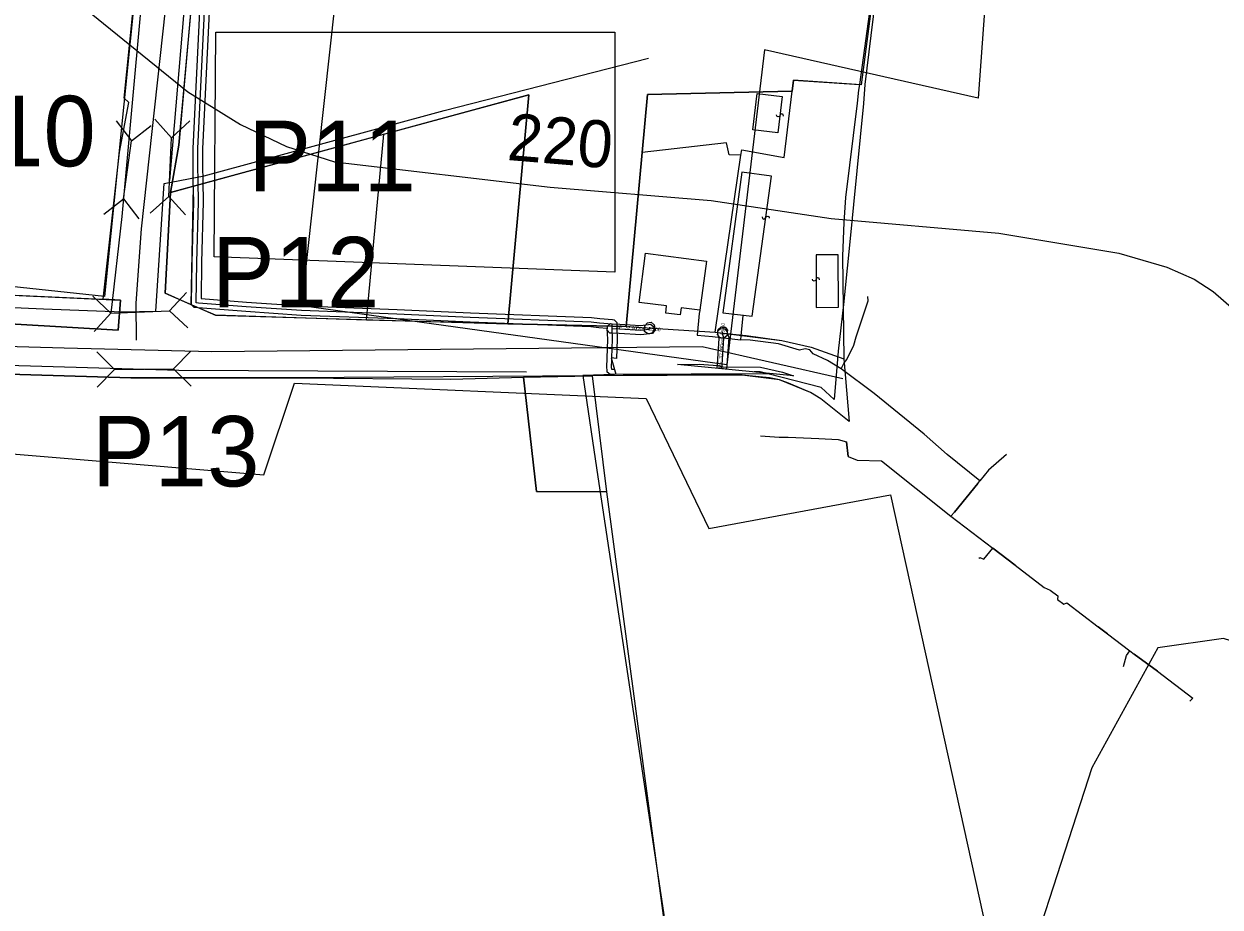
# Model space of a CAD drawing. Extents: x -662500 to -655523, y -1056000 to -1049993.
# Drawn here: x -660179.8 to -659925.2, y -1053965.2 to -1053777.2 of the extents above; entities that cross this region are included whole.
import ezdxf

# ---------------------------------------------------------------- set-up
doc = ezdxf.new("R2010")
doc.units = 0
for name, color, linetype in [('58', 7, 'Continuous'), ('Implicitní', 7, 'Continuous'), ('Vrstva 1', 7, 'Continuous'), ('Vrstva 11', 7, 'Continuous'), ('Vrstva 17', 7, 'Continuous'), ('Vrstva 24', 7, 'Continuous'), ('Vrstva 32', 7, 'Continuous'), ('Vrstva 37', 7, 'Continuous'), ('Vrstva 42', 7, 'Continuous'), ('Vrstva 45', 7, 'Continuous'), ('Vrstva 47', 7, 'Continuous'), ('Vrstva 48', 7, 'Continuous'), ('Vrstva 5', 7, 'Continuous'), ('Vrstva 61', 7, 'Continuous'), ('Vrstva 7', 7, 'Continuous')]:
    doc.layers.add(name, color=color, linetype=linetype)

# ---------------------------------------------------------------- blocks, each defined once
blk = doc.blocks.new('PSZ017')
at = {"layer": 'Vrstva 17'}
for points in [[(-10, 3.75), (-6.25, 0), (-10, -3.75)], [(10, 3.75), (6.25, 0), (10, -3.75)], [(-6.25, 0), (6.25, 0)]]:
    blk.add_lwpolyline(points, dxfattribs=at)
blk = doc.blocks.new('POINT_DISPLAY')
at = {"layer": 'Implicitní'}
blk.add_line((0, 0), (0, 0), dxfattribs=at)
blk = doc.blocks.new('$364')
at = {"layer": 'Implicitní'}
blk.add_lwpolyline([(-0.5, -7.5), (2.5, -6.5), (3.7, -3.4), (2.3, -0.7), (-2.5, 1), (-3.7, 3.8), (-2.3, 6.7), (0.5, 7.5)], dxfattribs=at)

msp = doc.modelspace()

# ---------------------------------------------------------------- linework, layer by layer
at = {"layer": '58'}
msp.add_lwpolyline([(-659966.09, -1053589.8), (-659979.45, -1053646.11), (-659986.05, -1053669.16), (-659992.56, -1053722.27), (-660000.86, -1053790.13), (-660001.11, -1053794.15), (-660003.29, -1053815.65), (-660003.85, -1053821.48), (-660005.39, -1053836.92), (-660006.52, -1053846.84), (-660007.35, -1053857.17), (-660010.12, -1053854.58), (-660021.49, -1053851.7), (-660054.09, -1053851.84), (-660060.83, -1053852), (-660057.69, -1053873.59), (-660041.94, -1053978.1)], dxfattribs=at)
at = {"layer": 'Vrstva 1'}
for p, q in [((-660106.89, -1053840.23), (-660103.21, -1053800.71)), ((-660144.25, -1053836.96), (-660143.69, -1053811.76))]:
    msp.add_line(p, q, dxfattribs=at)
for points in [[(-659954.06, -1053529.13), (-659973.69, -1053620.54), (-659985.28, -1053668.78), (-660002.01, -1053790.13), (-660002.16, -1053791.32), (-660002.5, -1053794.1), (-660004.94, -1053814.14), (-660005.18, -1053817.33), (-660005.34, -1053819.44), (-660005.58, -1053826.65), (-660005.29, -1053848.46), (-660004.16, -1053861.83), (-660010.2, -1053857.03), (-660012.44, -1053855.66), (-660017.12, -1053853.66), (-660019.03, -1053852.98), (-660021.16, -1053852.5), (-660026.92, -1053851.95), (-660035.99, -1053851.88), (-660050.1, -1053852.01), (-660052.3, -1053852.03), (-660058.85, -1053852.09), (-660055.8, -1053876.8), (-660042.1, -1053979.18)], [(-660051.64, -1053841.59), (-660048.25, -1053804.57), (-660047.13, -1053792.26), (-660016.34, -1053791.52), (-660016.06, -1053789.15), (-660002.01, -1053790.13)], [(-660032.72, -1053842.78), (-660027.21, -1053805.13), (-660027.04, -1053803.99), (-660017.98, -1053805.64), (-660016.34, -1053791.52)], [(-660027.21, -1053805.13), (-660029.72, -1053805.1), (-660030.32, -1053802.52), (-660048.25, -1053804.57)], [(-660051.64, -1053841.59), (-660032.72, -1053842.78), (-660031.72, -1053842.95), (-660026.12, -1053843.5), (-660018.51, -1053844.59), (-660012.27, -1053845.97), (-660005.29, -1053848.46)], [(-660055.8, -1053876.8), (-660070.7, -1053876.72), (-660073.51, -1053852.41), (-660058.85, -1053852.09)]]:
    msp.add_lwpolyline(points, dxfattribs=at)
for points in [[(-660148.64, -1053813.09), (-660143.69, -1053811.76), (-660103.21, -1053800.71), (-660072.33, -1053792.31), (-660076.83, -1053841.01), (-660106.89, -1053840.23), (-660139.06, -1053839.19), (-660144.25, -1053836.96), (-660149.76, -1053834.51)], [(-660023.73, -1053792.04), (-660018.42, -1053792.64), (-660019.34, -1053800.39), (-660024.7, -1053799.73)], [(-660027, -1053808.74), (-660031.07, -1053838.68), (-660024.79, -1053839.44), (-660020.73, -1053809.6)], [(-660047.53, -1053826.01), (-660034.52, -1053827.69), (-660035.98, -1053838.12), (-660039.93, -1053837.64), (-660040.15, -1053839.14), (-660043.23, -1053838.74), (-660043.04, -1053837.23), (-660048.89, -1053836.48)], [(-660011.23, -1053826.37), (-660011.22, -1053837.53), (-660006.47, -1053837.52), (-660006.5, -1053826.37)]]:
    msp.add_lwpolyline(points, close=True, dxfattribs=at)
at = {"layer": 'Vrstva 11'}
for points in [[(-660128.59, -1053535.41), (-660141.02, -1053666.13), (-660149.73, -1053774.2), (-660154.88, -1053820.83), (-660155.97, -1053836.63), (-660155.9, -1053844.5)], [(-660411.52, -1053823.45), (-660373.44, -1053828.35), (-660238.99, -1053844.22), (-660171.25, -1053846.11), (-660139.82, -1053846.95), (-660035.43, -1053845.88), (-660005.55, -1053852.66)]]:
    msp.add_lwpolyline(points, dxfattribs=at)
at = {"layer": 'Vrstva 17'}
for points in [[(-660093.08, -1053291.6), (-660096.38, -1053299.54), (-660103.97, -1053335.5), (-660111.56, -1053371.46), (-660148.84, -1053810.53)], [(-660409.95, -1053827.36), (-660292, -1053842.62), (-660239.28, -1053848.23), (-660146.85, -1053850.88), (-660072.84, -1053851.25)]]:
    msp.add_lwpolyline(points, dxfattribs=at)
at = {"layer": 'Vrstva 24'}
msp.add_lwpolyline([(-659830.33, -1054000), (-659832, -1053994), (-659843, -1053971.5), (-659874, -1053940), (-659913.5, -1053911.5), (-659924.5, -1053908), (-659938.5, -1053910), (-659952.5, -1053935.5), (-659971.5, -1053994), (-659976.58, -1054000)], dxfattribs=at)
at = {"layer": 'Vrstva 32'}
msp.add_lwpolyline([(-660407.56, -1053817.63), (-660406.83, -1053817.81), (-660364.13, -1053822.72), (-660321.75, -1053826.98), (-660286.16, -1053830.17), (-660234.71, -1053835.24), (-660175.64, -1053837.86), (-660158.79, -1053838.51), (-660151.75, -1053838.35), (-660149.96, -1053811.19), (-660141.45, -1053809.55), (-660090.4, -1053795.64), (-660046.88, -1053784.52)], dxfattribs=at)
at = {"layer": 'Vrstva 37'}
for points in [[(-660303.5, -1053230.44), (-660268.36, -1053230.44), (-660272.06, -1053456.27), (-660238.23, -1053464.08), (-660230.1, -1053441.95), (-660156.9, -1053423.64), (-660133.56, -1053315.41), (-660112.26, -1053315.31), (-660122.32, -1053372.39), (-660125.43, -1053404.18), (-660127.57, -1053442.13), (-660131.64, -1053497.5), (-660136.95, -1053566.03), (-660150.34, -1053712.33), (-660162.69, -1053835.19), (-660383.93, -1053811.56), (-660351.89, -1053606.5)], [(-660096.66, -1053668.18), (-659966.86, -1053657.36), (-659976.74, -1053792.99), (-660022.22, -1053782.75), (-660030.23, -1053849.74), (-660120.67, -1053837.24), (-660108.76, -1053729.2)], [(-660389.4, -1053839.98), (-660253.75, -1053862.77), (-660128.74, -1053873.18), (-660122.24, -1053853.65), (-660047.41, -1053856.91), (-660034.08, -1053884.58), (-659995.36, -1053877.42), (-659962.61, -1054026.33), (-660034.34, -1054033.17), (-660165.85, -1054002.41), (-660409.51, -1053977.34)]]:
    msp.add_lwpolyline(points, close=True, dxfattribs=at)
at = {"layer": 'Vrstva 42'}
for p, q in [((-660054.56, -1053844.32), (-660054.65, -1053842.02)), ((-660031.15, -1053843.07), (-660031.11, -1053842.73)), ((-660054.69, -1053848.29), (-660054.56, -1053844.32)), ((-660054.75, -1053850.28), (-660054.7, -1053848.69))]:
    msp.add_line(p, q, dxfattribs=at)
for points in [[(-660142.78, -1053807.34), (-660142.8, -1053803.76), (-660140.36, -1053754.17), (-660137.85, -1053724), (-660136.78, -1053713.11), (-660133.93, -1053679.11), (-660128.02, -1053621.83), (-660127.49, -1053612.47), (-660120.96, -1053547.99), (-660119.87, -1053525.87), (-660118.25, -1053505.95), (-660116.02, -1053485.23), (-660115.83, -1053483.2)], [(-660142.66, -1053836.62), (-660143.12, -1053836.59), (-660143.01, -1053828), (-660142.63, -1053815.06), (-660142.76, -1053810.73), (-660142.78, -1053807.34)], [(-660054.65, -1053842.02), (-660054.64, -1053841.13), (-660057.34, -1053840.88), (-660059.11, -1053840.7), (-660084.83, -1053839.68), (-660100.44, -1053838.97), (-660120.72, -1053838.23), (-660132.51, -1053837.4), (-660142.66, -1053836.62)], [(-660054.65, -1053842.02), (-660053.07, -1053842.11), (-660048.58, -1053842.38), (-660046.77, -1053842.15)], [(-660046.77, -1053842.15), (-660046.56, -1053842.12), (-660046.6, -1053841.74)], [(-660030.82, -1053844.06), (-660031.15, -1053843.11), (-660031.15, -1053843.07)], [(-660031.29, -1053850.59), (-660031.22, -1053849.67), (-660030.82, -1053844.06)], [(-660054.11, -1053850.77), (-660054.7, -1053850.79), (-660054.75, -1053850.28)], [(-660022.27, -1053851.47), (-660023.14, -1053851.27), (-660024.42, -1053851.26)]]:
    msp.add_lwpolyline(points, dxfattribs=at)
for points in [[(-660047.76, -1053842.27), (-660047.82, -1053841.86), (-660047.62, -1053841.61), (-660047.64, -1053841.43), (-660047.12, -1053840.79), (-660046.71, -1053840.74), (-660046.3, -1053840.7), (-660045.65, -1053841.22), (-660045.61, -1053841.63), (-660045.57, -1053842.01), (-660045.52, -1053842.42), (-660046.03, -1053843.06), (-660046.43, -1053843.11), (-660046.64, -1053843.14), (-660047.05, -1053843.19), (-660047.71, -1053842.69)], [(-660055.62, -1053841.55), (-660055, -1053841), (-660054.59, -1053841.02), (-660053.01, -1053841.11), (-660048.61, -1053841.37), (-660046.9, -1053841.16), (-660046.49, -1053841.1), (-660045.83, -1053841.61), (-660045.78, -1053842.02), (-660045.72, -1053842.43), (-660046.23, -1053843.09), (-660046.64, -1053843.14), (-660048.55, -1053843.38), (-660053.13, -1053843.11), (-660054.7, -1053843.02), (-660055.12, -1053842.99), (-660055.67, -1053842.37), (-660055.64, -1053841.96)], [(-660030.28, -1053850.69), (-660032.29, -1053850.49), (-660032.22, -1053849.59), (-660031.83, -1053844.19), (-660032.16, -1053843.23), (-660032.14, -1053842.99), (-660032.1, -1053842.57), (-660031.47, -1053842.04), (-660031.06, -1053842.08), (-660030.64, -1053842.11), (-660030.11, -1053842.75), (-660030.13, -1053842.98), (-660029.81, -1053843.92), (-660030.23, -1053849.74), (-660030.29, -1053850.63)], [(-660031.66, -1053844.03), (-660032.18, -1053843.38), (-660032.14, -1053842.97), (-660032.1, -1053842.63), (-660032.06, -1053842.22), (-660031.42, -1053841.7), (-660031.01, -1053841.74), (-660030.6, -1053841.78), (-660030.07, -1053842.42), (-660030.11, -1053842.83), (-660030.15, -1053843.18), (-660030.19, -1053843.59), (-660030.83, -1053844.11), (-660031.25, -1053844.07)], [(-660016, -1053852.09), (-660040.68, -1053849.67), (-660036.1, -1053849.6), (-660032.16, -1053849.92), (-660031.07, -1053850.19), (-660023.02, -1053850.28), (-660018.35, -1053851.34)], [(-660016, -1053852.09), (-660040.68, -1053849.67), (-660036.1, -1053849.6), (-660032.16, -1053849.92), (-660031.07, -1053850.19), (-660023.02, -1053850.28), (-660018.35, -1053851.34)], [(-660016, -1053852.09), (-660040.68, -1053849.67), (-660036.1, -1053849.6), (-660032.16, -1053849.92), (-660031.07, -1053850.19), (-660023.02, -1053850.28), (-660018.35, -1053851.34)]]:
    msp.add_lwpolyline(points, close=True, dxfattribs=at)
at = {"layer": 'Vrstva 45'}
for p, q in [((-660019.23, -1053845.3), (-660025.28, -1053844.53)), ((-660019.23, -1053845.3), (-660025.28, -1053844.53)), ((-660004.37, -1053869.26), (-660004.73, -1053866.12)), ((-660004.37, -1053869.26), (-660004.73, -1053866.12)), ((-659983.31, -1053868.82), (-659988.2, -1053864.53)), ((-659983.31, -1053868.82), (-659988.2, -1053864.53)), ((-659976.77, -1053874.99), (-659981.78, -1053881.13)), ((-659976.77, -1053874.99), (-659981.78, -1053881.13)), ((-659982.51, -1053881.96), (-659973.58, -1053888.81)), ((-659982.51, -1053881.96), (-659973.58, -1053888.81)), ((-659968.87, -1053892.36), (-659973.58, -1053888.81)), ((-659968.87, -1053892.36), (-659973.58, -1053888.81)), ((-659949.17, -1053907.04), (-659951.18, -1053905.54)), ((-659949.17, -1053907.04), (-659951.18, -1053905.54)), ((-659938.55, -1053914.97), (-659943.54, -1053911.33)), ((-659938.55, -1053914.97), (-659943.54, -1053911.33)), ((-659931.7, -1053921.37), (-659931.02, -1053920.67)), ((-659931.7, -1053921.37), (-659931.02, -1053920.67))]:
    msp.add_line(p, q, dxfattribs=at)
for points in [[(-660005.9, -1053850.61), (-660005.22, -1053849.31), (-660004.7, -1053848.66), (-660003.21, -1053845.61), (-660002.71, -1053843.77), (-660000.16, -1053836.14), (-660000.23, -1053835.19)], [(-660005.9, -1053850.61), (-660005.22, -1053849.31), (-660004.7, -1053848.66), (-660003.21, -1053845.61), (-660002.71, -1053843.77), (-660000.16, -1053836.14), (-660000.23, -1053835.19)], [(-660035.98, -1053838.17), (-660036.09, -1053838.87), (-660036.5, -1053843.45), (-660033.25, -1053843.74), (-660027.34, -1053844.46)], [(-660035.98, -1053838.17), (-660036.09, -1053838.87), (-660036.5, -1053843.45), (-660033.25, -1053843.74), (-660027.34, -1053844.46)], [(-660026.8, -1053839.27), (-660027.24, -1053843.61), (-660027.34, -1053844.46)], [(-660026.8, -1053839.27), (-660027.24, -1053843.61), (-660027.34, -1053844.46)], [(-660005.9, -1053850.61), (-660008.78, -1053848.86), (-660011.84, -1053847.41), (-660012.55, -1053846.6), (-660013.55, -1053846.38), (-660014.74, -1053846.62), (-660019.23, -1053845.3), (-660025.28, -1053844.53), (-660027.34, -1053844.46)], [(-660005.9, -1053850.61), (-660008.78, -1053848.86), (-660011.84, -1053847.41), (-660012.55, -1053846.6), (-660013.55, -1053846.38), (-660014.74, -1053846.62), (-660019.23, -1053845.3), (-660025.28, -1053844.53), (-660027.34, -1053844.46)], [(-659976.34, -1053874.46), (-659983.31, -1053868.82), (-659988.2, -1053864.53), (-659998.87, -1053855.83), (-660005.9, -1053850.61)], [(-659976.34, -1053874.46), (-659983.31, -1053868.82), (-659988.2, -1053864.53), (-659998.87, -1053855.83), (-660005.9, -1053850.61)], [(-660023.06, -1053864.89), (-660019.07, -1053865.13), (-660017.17, -1053865.15), (-660010.67, -1053865.42), (-660006.5, -1053865.67), (-660004.73, -1053866.12), (-660004.37, -1053869.26), (-660002.45, -1053870.04), (-659997.27, -1053870.21), (-659982.51, -1053881.96)], [(-660023.06, -1053864.89), (-660019.07, -1053865.13), (-660017.17, -1053865.15), (-660010.67, -1053865.42), (-660006.5, -1053865.67), (-660004.73, -1053866.12), (-660004.37, -1053869.26), (-660002.45, -1053870.04), (-659997.27, -1053870.21), (-659982.51, -1053881.96)], [(-659970.71, -1053868.82), (-659974.56, -1053872.16), (-659976.34, -1053874.46)], [(-659970.71, -1053868.82), (-659974.56, -1053872.16), (-659976.34, -1053874.46)], [(-659982.51, -1053881.96), (-659981.78, -1053881.13), (-659976.77, -1053874.99), (-659976.34, -1053874.46)], [(-659982.51, -1053881.96), (-659981.78, -1053881.13), (-659976.77, -1053874.99), (-659976.34, -1053874.46)], [(-659976.54, -1053890.95), (-659976.39, -1053890.74), (-659975.53, -1053891.1), (-659973.58, -1053888.81)], [(-659976.54, -1053890.95), (-659976.39, -1053890.74), (-659975.53, -1053891.1), (-659973.58, -1053888.81)], [(-659973.58, -1053888.81), (-659968.87, -1053892.36), (-659962.67, -1053897.15), (-659961.37, -1053897.74), (-659959.77, -1053898.94), (-659959.82, -1053899.67), (-659958.47, -1053900.69), (-659957.84, -1053900.44), (-659951.18, -1053905.54), (-659949.17, -1053907.04), (-659944.43, -1053910.65)], [(-659973.58, -1053888.81), (-659968.87, -1053892.36), (-659962.67, -1053897.15), (-659961.37, -1053897.74), (-659959.77, -1053898.94), (-659959.82, -1053899.67), (-659958.47, -1053900.69), (-659957.84, -1053900.44), (-659951.18, -1053905.54), (-659949.17, -1053907.04), (-659944.43, -1053910.65)], [(-659945.76, -1053913.98), (-659945.19, -1053911.6), (-659944.43, -1053910.65)], [(-659945.76, -1053913.98), (-659945.19, -1053911.6), (-659944.43, -1053910.65)], [(-659944.43, -1053910.65), (-659943.54, -1053911.33), (-659938.55, -1053914.97), (-659931.02, -1053920.67)], [(-659944.43, -1053910.65), (-659943.54, -1053911.33), (-659938.55, -1053914.97), (-659931.02, -1053920.67)]]:
    msp.add_lwpolyline(points, dxfattribs=at)
at = {"layer": 'Vrstva 47'}
for points in [[(-660136.85, -1053724.09), (-660139.36, -1053754.23), (-660141.8, -1053803.78), (-660141.78, -1053807.33), (-660141.76, -1053810.72), (-660141.63, -1053815.06), (-660142.01, -1053828.02), (-660142.11, -1053835.66), (-660132.43, -1053836.41), (-660120.67, -1053837.24), (-660100.4, -1053837.97), (-660084.79, -1053838.68), (-660059.04, -1053839.7), (-660057.24, -1053839.89), (-660054.55, -1053840.13), (-660054.17, -1053840.17), (-660053.64, -1053840.74), (-660053.64, -1053841.13), (-660053.65, -1053842), (-660053.56, -1053844.32), (-660053.69, -1053848.39), (-660054.82, -1053848.28)], [(-660054.82, -1053848.28), (-660053.83, -1053851.76), (-660054.66, -1053851.79), (-660055.06, -1053851.81), (-660055.65, -1053851.29), (-660055.69, -1053850.9), (-660055.75, -1053850.32), (-660055.57, -1053844.33), (-660055.65, -1053842.04), (-660057.44, -1053841.88), (-660059.19, -1053841.69), (-660084.87, -1053840.68), (-660100.48, -1053839.97), (-660120.78, -1053839.23), (-660132.58, -1053838.4), (-660142.73, -1053837.62), (-660143.2, -1053837.59), (-660143.59, -1053837.56), (-660144.13, -1053836.97), (-660144.12, -1053836.58), (-660144.01, -1053827.98), (-660143.63, -1053815.06), (-660143.76, -1053810.75), (-660143.78, -1053807.34), (-660143.8, -1053803.74), (-660141.36, -1053754.1)]]:
    msp.add_lwpolyline(points, dxfattribs=at)
at = {"layer": 'Vrstva 48'}
msp.add_lwpolyline([(-660138.99, -1053778.97), (-660054.08, -1053778.97), (-660054.08, -1053830.07), (-660139.31, -1053826.81)], close=True, dxfattribs=at)
at = {"layer": 'Vrstva 5'}
for points in [[(-659953.22, -1053525.2), (-659985.7, -1053668.71), (-660001.66, -1053790.17), (-660016.06, -1053789.15), (-660016.34, -1053791.52), (-660047.13, -1053792.26), (-660051.64, -1053841.59), (-660076.83, -1053841.01), (-660072.33, -1053792.31), (-660148.64, -1053813.09), (-660146.82, -1053803.03), (-660144.24, -1053774.31), (-660138.85, -1053712.12), (-660126.59, -1053589.2)], [(-660728.84, -1053594.86), (-660659.38, -1053604.53), (-660591.82, -1053615.12), (-660481.41, -1053634.1), (-660378.28, -1053653.76), (-660398.86, -1053759.98), (-660407.77, -1053814.99), (-660406.28, -1053815.33), (-660305.92, -1053826.68), (-660234.87, -1053832.54), (-660162.97, -1053835.81), (-660159.44, -1053804.48), (-660157.5, -1053793.95), (-660158.49, -1053793), (-660150.34, -1053712.33), (-660136.95, -1053566.03)], [(-660235.12, -1053837.99), (-660159.73, -1053842.4), (-660159.25, -1053835.99), (-660162.97, -1053835.81), (-660159.44, -1053804.48), (-660157.5, -1053793.95), (-660158.49, -1053793), (-660150.34, -1053712.33), (-660136.95, -1053566.03)], [(-660126.59, -1053589.2), (-660138.85, -1053712.12), (-660146.82, -1053803.03), (-660148.64, -1053813.09), (-660149.76, -1053834.51), (-660139.06, -1053839.19), (-660076.83, -1053841.01), (-660051.64, -1053841.59), (-660032.72, -1053842.78), (-660018.51, -1053844.59), (-660012.27, -1053845.97), (-660005.29, -1053848.46), (-660004.16, -1053861.83), (-660010.2, -1053857.03), (-660012.44, -1053855.66), (-660019.03, -1053852.98), (-660026.92, -1053851.95), (-660058.85, -1053852.09), (-660122.2, -1053852.55), (-660157.09, -1053852.56), (-660239.81, -1053850.04)]]:
    msp.add_lwpolyline(points, dxfattribs=at)
for points in [[(-660407.77, -1053814.99), (-660406.28, -1053815.33), (-660305.92, -1053826.68), (-660234.87, -1053832.54), (-660159.25, -1053835.99), (-660159.73, -1053842.4), (-660235.12, -1053837.99), (-660406.12, -1053820.42), (-660408.56, -1053819.81)], [(-660410.34, -1053829.44), (-660358.01, -1053836.31), (-660307.68, -1053842.9), (-660239.81, -1053850.04), (-660157.09, -1053852.56), (-660122.2, -1053852.55), (-660088.98, -1053852.83), (-660073.51, -1053852.41), (-660070.7, -1053876.72), (-660055.8, -1053876.8), (-660042.1, -1053979.18), (-660077.54, -1053979.35), (-660076.72, -1054000.14), (-660201.14, -1054026.33), (-660241.12, -1054042.52), (-660324.21, -1054084.16), (-660365.41, -1054097.44), (-660421.6, -1054104.02), (-660440.68, -1054035.17), (-660444.92, -1054007.24), (-660438.94, -1053983.58)]]:
    msp.add_lwpolyline(points, close=True, dxfattribs=at)
at = {"layer": 'Vrstva 61'}
msp.add_lwpolyline([(-660103.33, -1053285.76), (-660108.12, -1053300.67), (-660119.61, -1053361.23), (-660123.15, -1053400.36), (-660134.78, -1053552.31), (-660158.95, -1053818.23), (-660161.28, -1053838.75)], dxfattribs=at)
at = {"layer": 'Vrstva 7'}
for p, q in [((-660179.92, -1053763.19), (-660144.92, -1053791.67)), ((-660144.92, -1053791.67), (-660133.72, -1053798.62)), ((-660133.72, -1053798.62), (-660123.95, -1053803.29)), ((-660123.95, -1053803.29), (-660113.74, -1053806.55)), ((-660113.74, -1053806.55), (-660067.83, -1053811.94)), ((-660067.83, -1053811.94), (-660033.53, -1053814.77)), ((-660033.53, -1053814.77), (-660008.02, -1053818.6)), ((-660008.02, -1053818.6), (-659972.31, -1053821.72)), ((-659972.31, -1053821.72), (-659946.8, -1053825.97)), ((-659946.8, -1053825.97), (-659936.6, -1053828.95)), ((-659936.6, -1053828.95), (-659930.79, -1053831.5)), ((-659930.79, -1053831.5), (-659926.68, -1053834.19)), ((-659926.68, -1053834.19), (-659917.32, -1053842.41))]:
    msp.add_line(p, q, dxfattribs=at)

# ---------------------------------------------------------------- block references
at = {"layer": 'Vrstva 1', "xscale": 0.1}
for p, yscale, rotation in [((-660018.9, -1053796.69), 0.09999999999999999, 83.22784899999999), ((-660021.93, -1053818.43), 0.10000000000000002, -97.74576200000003), ((-660011.23, -1053831.6), 0.10000000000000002, 90.051775)]:
    msp.add_blockref('$364', p, dxfattribs=dict(at, yscale=yscale, rotation=rotation))
at = {"layer": 'Vrstva 1', "xscale": 0.1, "yscale": 0.10000000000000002}
for p in [(-660027.04, -1053803.99), (-660043.04, -1053837.23), (-660031.07, -1053838.68)]:
    msp.add_blockref('POINT_DISPLAY', p, dxfattribs=at)
at = {"layer": 'Vrstva 17'}
for p, rotation in [((-660148.69, -1053807.67), 87.25759419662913), ((-660157.76, -1053808.26), 82.39672901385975), ((-660155.04, -1053838.51), 2.1570637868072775), ((-660154.26, -1053850.67), 0.5686235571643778)]:
    msp.add_blockref('PSZ017', p, dxfattribs=dict(at, rotation=rotation))

# ---------------------------------------------------------------- texts
for s, p in [('P10', (-660200.19, -1053807.51)), ('P11', (-660132.06, -1053812.81)), ('P12', (-660139.83, -1053837.54)), ('P13', (-660165.37, -1053875.65))]:
    msp.add_text(s, height=15, rotation=360, dxfattribs=at).set_placement(p)
at = {"layer": 'Vrstva 42'}
for s, rotation, p in [('PE  32.00', 356.5623, (-660053.86, -1053842.07)), ('Ocel  25.00', 356.5623, (-660049.61, -1053842.32)), ('Ocel  25.00', 85.9437, (-660030.97, -1053846.17)), ('PE  32.00', 85.9437, (-660031.28, -1053850.43))]:
    msp.add_text(s, height=0.75, rotation=rotation, dxfattribs=at).set_placement(p)
at = {"layer": 'Vrstva 7'}
msp.add_text('220', height=10, rotation=355.2762, dxfattribs=at).set_placement((-660077.16, -1053806.15))

doc.saveas('drawing.dxf')
